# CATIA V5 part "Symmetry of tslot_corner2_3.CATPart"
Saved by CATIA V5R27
Part number: Symmetry of tslot_corner2_3
Bounding box of the stored display mesh (mm): x -19.05 to 19.05, y -19.05 to 19.05, z -1374.764 to -1219.2
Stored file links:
  \\triton.meca.polymtl.ca\usagers\zaoue\profiles\Desktop\varm_ass\structure prismatique\Symmetry of tslot_corner2_3.CATPart
  \\triton.meca.polymtl.ca\usagers\zaoue\profiles\Desktop\varm_ass\structure prismatique\tslot_corner2.CATPart
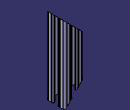
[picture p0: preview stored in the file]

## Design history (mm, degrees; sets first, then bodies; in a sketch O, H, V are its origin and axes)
Body1 (main body)
Body2 "Boss-Extrude1"
  Solid1: linked copy from another document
